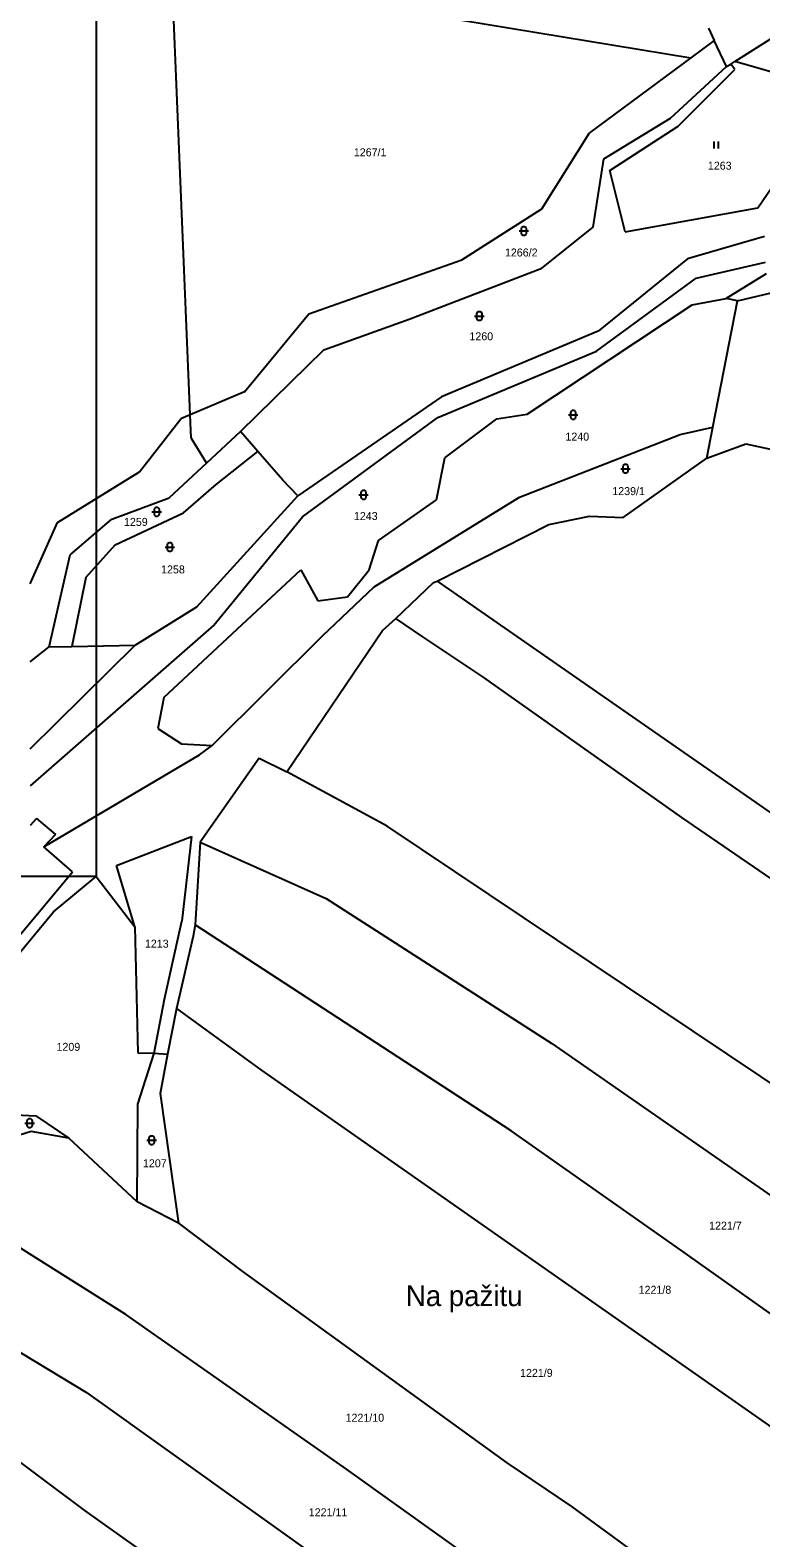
# Model space of a CAD drawing. Extents: x -799786 to -795190, y -1021716 to -1017834.
# Drawn here: x -798434.2 to -798278.5, y -1019350.1 to -1019029 of the extents above; entities that cross this region are included whole.
import ezdxf

# ---------------------------------------------------------------- set-up
doc = ezdxf.new("R2010")
doc.units = 0
for name, color, linetype in [('Default', 7, 'Continuous'), ('KN_HRANICE', 7, 'Continuous'), ('KN_KULTURY', 7, 'Continuous'), ('KN_PARCELY', 7, 'Continuous'), ('LEGENDA', 7, 'Continuous')]:
    doc.layers.add(name, color=color, linetype=linetype)

# ---------------------------------------------------------------- blocks, each defined once
blk = doc.blocks.new('306')
at = {"layer": 'Default'}
for p, q in [((-0.5, 1.5), (-0.5, 0)), ((0.5, 0), (0.5, 1.5))]:
    blk.add_line(p, q, dxfattribs=at)
blk = doc.blocks.new('316')
at = {"layer": 'Default'}
for points in [[(-1, 1), (0.27, 1), (1, 1)], [(-0.5, 1.5), (-0.4, 1.79), (-0.15, 1.97), (0.16, 1.97), (0.41, 1.79), (0.51, 1.5), (0.51, 0.5), (0.41, 0.21), (0.16, 0.03), (-0.15, 0.03), (-0.4, 0.21), (-0.5, 0.5), (-0.5, 1.5)]]:
    blk.add_lwpolyline(points, dxfattribs=at)

msp = doc.modelspace()

# ---------------------------------------------------------------- linework, layer by layer
at = {"layer": 'KN_HRANICE'}
for p, q in [((-798400.12, -1019110.95), (-798404.09, -1019014.54)), ((-798359.05, -1019024.1), (-798293.45, -1019034.91)), ((-798284.03, -1019035.68), (-798271.37, -1019027.66)), ((-798289.67, -1019028.59), (-798288.5, -1019031.25)), ((-798288.5, -1019031.25), (-798293.45, -1019034.91)), ((-798285.82, -1019036.77), (-798288.5, -1019031.25)), ((-798293.45, -1019034.91), (-798315.04, -1019050.85)), ((-798297.8, -1019047.77), (-798285.82, -1019036.77)), ((-798285.82, -1019036.77), (-798284.92, -1019036.23)), ((-798284.92, -1019036.23), (-798284.03, -1019035.68)), ((-798284.03, -1019037.42), (-798284.92, -1019036.23)), ((-798268.28, -1019040.2), (-798284.03, -1019035.68)), ((-798296.11, -1019049.46), (-798284.03, -1019037.42)), ((-798311.96, -1019056.41), (-798297.8, -1019047.77)), ((-798310.72, -1019058.9), (-798296.11, -1019049.46)), ((-798325.18, -1019067.07), (-798315.04, -1019050.85)), ((-798279.13, -1019066.87), (-798269.48, -1019052.64)), ((-798314.25, -1019070.99), (-798311.96, -1019056.41)), ((-798307.44, -1019071.99), (-798310.72, -1019058.9)), ((-798342.22, -1019077.92), (-798325.18, -1019067.07)), ((-798307.44, -1019071.99), (-798279.13, -1019066.87)), ((-798325.18, -1019079.73), (-798314.25, -1019070.99)), ((-798277.73, -1019072.94), (-798294.15, -1019077.72)), ((-798374.85, -1019089.46), (-798342.22, -1019077.92)), ((-798294.15, -1019077.72), (-798313.2, -1019093.11)), ((-798292.31, -1019081.83), (-798277.52, -1019078.42)), ((-798353.46, -1019090.56), (-798325.18, -1019079.73)), ((-798313.51, -1019097.35), (-798292.31, -1019081.83)), ((-798277.42, -1019080.9), (-798285.9, -1019086.17)), ((-798283.51, -1019086.63), (-798272.14, -1019083.99)), ((-798328.29, -1019110.8), (-798293.14, -1019087.52)), ((-798293.14, -1019087.52), (-798285.9, -1019086.17)), ((-798288.76, -1019113.55), (-798283.51, -1019086.63)), ((-798283.51, -1019086.63), (-798285.9, -1019086.17)), ((-798388.54, -1019106.05), (-798374.85, -1019089.46)), ((-798371.66, -1019097.13), (-798353.46, -1019090.56)), ((-798313.2, -1019093.11), (-798346.6, -1019107.08)), ((-798389.43, -1019114.51), (-798371.66, -1019097.13)), ((-798347.32, -1019111.52), (-798313.51, -1019097.35)), ((-798388.54, -1019106.05), (-798400.12, -1019110.95)), ((-798346.6, -1019107.08), (-798377.17, -1019128.23)), ((-798400.12, -1019110.95), (-798402.14, -1019111.8)), ((-798399.92, -1019115.9), (-798400.12, -1019110.95)), ((-798334.81, -1019111.83), (-798328.29, -1019110.8)), ((-798410.89, -1019123.09), (-798402.14, -1019111.8)), ((-798376.17, -1019132.7), (-798347.32, -1019111.52)), ((-798345.85, -1019120.08), (-798334.81, -1019111.83)), ((-798295.7, -1019115.11), (-798288.76, -1019113.55)), ((-798290.05, -1019120.17), (-798288.76, -1019113.55)), ((-798399.92, -1019115.9), (-798396.65, -1019121.23)), ((-798389.43, -1019114.51), (-798396.65, -1019121.23)), ((-798385.72, -1019118.74), (-798389.43, -1019114.51)), ((-798329.93, -1019128.46), (-798295.7, -1019115.11)), ((-798290.05, -1019120.17), (-798281.71, -1019117.15)), ((-798281.71, -1019117.15), (-798270.95, -1019119.48)), ((-798394.6, -1019125.76), (-798385.72, -1019118.74)), ((-798380.38, -1019124.89), (-798385.72, -1019118.74)), ((-798347.61, -1019129.08), (-798345.85, -1019120.08)), ((-798307.85, -1019132.82), (-798290.05, -1019120.17)), ((-798428.38, -1019133.84), (-798410.89, -1019123.09)), ((-798396.65, -1019121.23), (-798404.61, -1019128.63)), ((-798401.54, -1019131.84), (-798394.6, -1019125.76)), ((-798377.17, -1019128.23), (-798380.38, -1019124.89)), ((-798416.83, -1019133.17), (-798404.61, -1019128.63)), ((-798398.71, -1019151.85), (-798377.17, -1019128.23)), ((-798360.92, -1019147.57), (-798329.93, -1019128.46)), ((-798359.99, -1019137.74), (-798347.61, -1019129.08)), ((-798425.69, -1019140.76), (-798416.83, -1019133.17)), ((-798416.1, -1019138.65), (-798401.54, -1019131.84)), ((-798395.06, -1019155.75), (-798376.17, -1019132.7)), ((-798323.68, -1019134.33), (-798315, -1019132.53)), ((-798315, -1019132.53), (-798307.85, -1019132.82)), ((-798434.21, -1019146.97), (-798428.38, -1019133.84)), ((-798347.52, -1019146.35), (-798323.68, -1019134.33)), ((-798422.35, -1019145.57), (-798416.1, -1019138.65)), ((-798361.95, -1019143.95), (-798359.99, -1019137.74)), ((-798430.16, -1019160.33), (-798425.69, -1019140.76)), ((-798422.35, -1019145.57), (-798425.35, -1019160.26)), ((-798405.77, -1019171.12), (-798376.53, -1019143.95)), ((-798376.53, -1019143.95), (-798372.91, -1019150.57)), ((-798366.6, -1019149.74), (-798361.95, -1019143.95)), ((-798348.29, -1019146.68), (-798347.52, -1019146.35)), ((-798347.52, -1019146.35), (-798176.91, -1019264.88)), ((-798371.95, -1019157.98), (-798360.92, -1019147.57)), ((-798356.31, -1019154.31), (-798348.29, -1019146.68)), ((-798411.87, -1019160), (-798398.71, -1019151.85)), ((-798372.91, -1019150.57), (-798366.6, -1019149.74)), ((-798395.06, -1019155.75), (-798434.21, -1019189.94)), ((-798359.11, -1019156.9), (-798356.31, -1019154.31)), ((-798350.55, -1019158.22), (-798356.31, -1019154.31)), ((-798395.43, -1019181.36), (-798371.95, -1019157.98)), ((-798379.56, -1019186.95), (-798359.11, -1019156.9)), ((-798337.52, -1019166.91), (-798350.55, -1019158.22)), ((-798434.21, -1019182.07), (-798411.87, -1019160)), ((-798434.21, -1019163.57), (-798430.16, -1019160.33)), ((-798430.16, -1019160.33), (-798425.35, -1019160.26)), ((-798425.35, -1019160.26), (-798411.87, -1019160)), ((-798295.35, -1019196.67), (-798337.52, -1019166.91)), ((-798405.77, -1019171.12), (-798407.01, -1019177.74)), ((-798407.01, -1019177.74), (-798401.94, -1019181.05)), ((-798401.94, -1019181.05), (-798395.43, -1019181.36)), ((-798398.13, -1019183.37), (-798395.43, -1019181.36)), ((-798431.28, -1019202.97), (-798398.13, -1019183.37)), ((-798385.45, -1019184.05), (-798397.97, -1019201.95)), ((-798385.45, -1019184.05), (-798379.56, -1019186.95)), ((-798358.17, -1019198.54), (-798379.56, -1019186.95)), ((-798432.88, -1019196.92), (-798434.21, -1019198.43)), ((-798432.88, -1019196.92), (-798428.85, -1019200.33)), ((-798236.26, -1019237.37), (-798295.35, -1019196.67)), ((-798428.85, -1019200.33), (-798431.28, -1019202.97)), ((-798415.85, -1019206.94), (-798399.81, -1019200.77)), ((-798399.81, -1019200.77), (-798401.87, -1019218.77)), ((-798269.58, -1019257.87), (-798358.17, -1019198.54)), ((-798425.19, -1019208.25), (-798431.28, -1019202.97)), ((-798397.97, -1019201.95), (-798399.08, -1019219.6)), ((-798397.97, -1019201.95), (-798371.17, -1019213.94)), ((-798411.9, -1019220.01), (-798415.85, -1019206.94)), ((-798458.53, -1019248.28), (-798425.19, -1019208.25)), ((-798429.28, -1019216.81), (-798420.18, -1019209.26)), ((-798420.18, -1019209.26), (-798411.9, -1019220.01)), ((-798371.17, -1019213.94), (-798323.08, -1019244.85)), ((-798456.62, -1019249.78), (-798429.28, -1019216.81)), ((-798411.9, -1019220.01), (-798411.26, -1019246.84)), ((-798405.6, -1019235.43), (-798401.87, -1019218.77)), ((-798399.08, -1019219.6), (-798399.5, -1019221.98)), ((-798331.7, -1019263.44), (-798399.08, -1019219.6)), ((-798399.5, -1019221.98), (-798403.01, -1019237.4)), ((-798407.77, -1019246.91), (-798405.6, -1019235.43)), ((-798403.01, -1019237.4), (-798404.98, -1019247.1)), ((-798403.01, -1019237.4), (-798385.05, -1019250.48)), ((-798323.08, -1019244.85), (-798216.61, -1019318.7)), ((-798411.28, -1019257.77), (-798407.77, -1019246.91)), ((-798411.26, -1019246.84), (-798407.77, -1019246.91)), ((-798407.77, -1019246.91), (-798404.98, -1019247.1)), ((-798404.98, -1019247.1), (-798406.53, -1019255.48)), ((-798385.05, -1019250.48), (-798240.9, -1019351.36)), ((-798406.53, -1019255.48), (-798402.6, -1019283.09)), ((-798411.39, -1019278.54), (-798411.28, -1019257.77)), ((-798441.91, -1019259.81), (-798433.02, -1019260.22)), ((-798433.02, -1019260.22), (-798425.97, -1019264.99)), ((-798434, -1019263.58), (-798451.99, -1019269.12)), ((-798425.97, -1019264.99), (-798434, -1019263.58)), ((-798411.39, -1019278.54), (-798425.97, -1019264.99)), ((-798295.38, -1019289), (-798331.7, -1019263.44)), ((-798413.87, -1019302.58), (-798455.66, -1019276.2)), ((-798402.6, -1019283.09), (-798411.39, -1019278.54)), ((-798402.6, -1019283.09), (-798388.96, -1019293.42)), ((-798172.28, -1019376.09), (-798295.38, -1019289)), ((-798388.96, -1019293.42), (-798332.63, -1019334.12)), ((-798458.48, -1019297.36), (-798422.2, -1019319.14)), ((-798366.78, -1019335.52), (-798413.87, -1019302.58)), ((-798422.56, -1019344.32), (-798456.65, -1019318.8)), ((-798422.2, -1019319.14), (-798299.96, -1019406.46)), ((-798267.29, -1019406.58), (-798366.78, -1019335.52)), ((-798332.63, -1019334.12), (-798318.88, -1019343.43)), ((-798336.15, -1019405.61), (-798422.56, -1019344.32)), ((-798318.88, -1019343.43), (-798278.8, -1019372.75))]:
    msp.add_line(p, q, dxfattribs=at)
at = {"layer": 'LEGENDA'}
msp.add_lwpolyline([(-799014.18, -1018789.26), (-798420.18, -1018789.26), (-798420.18, -1019209.26), (-799014.18, -1019209.26)], close=True, dxfattribs=at)

# ---------------------------------------------------------------- block references
at = {"layer": 'KN_KULTURY'}
for name, p in [('306', (-798288.02, -1019054.24)), ('316', (-798329.03, -1019072.79)), ('316', (-798338.51, -1019090.9)), ('316', (-798318.49, -1019111.95)), ('316', (-798307.36, -1019123.42)), ('316', (-798363.18, -1019128.99)), ('316', (-798407.26, -1019132.6)), ('316', (-798404.46, -1019140.1)), ('316', (-798434.33, -1019262.8)), ('316', (-798408.33, -1019266.45))]:
    msp.add_blockref(name, p, dxfattribs=at)

# ---------------------------------------------------------------- texts
at = {"layer": 'KN_PARCELY'}
for s, height, p in [('1267/1', 1.7, (-798365.25, -1019055.88)), ('1263', 1.7, (-798289.81, -1019058.73)), ('1266/2', 1.7, (-798333.05, -1019077.22)), ('1260', 1.7, (-798340.62, -1019095.07)), ('1240', 1.7, (-798320.16, -1019116.44)), ('1239/1', 1.7, (-798310.17, -1019128.04)), ('1259', 1.7, (-798414.23, -1019134.59)), ('1243', 1.7, (-798365.23, -1019133.35)), ('1258', 1.7, (-798406.32, -1019144.72)), ('1213', 1.7, (-798409.77, -1019224.43)), ('1209', 1.7, (-798428.61, -1019246.4)), ('1207', 1.7, (-798410.19, -1019271.2)), ('1221/7', 1.7, (-798289.54, -1019284.48)), ('Na pažitu', 4.4, (-798354.16, -1019300.77)), ('1221/8', 1.7, (-798304.56, -1019298.14)), ('1221/9', 1.7, (-798329.83, -1019315.84)), ('1221/10', 1.7, (-798367.01, -1019325.39)), ('1221/11', 1.7, (-798374.86, -1019345.53))]:
    msp.add_text(s, height=height, dxfattribs=at).set_placement(p)

doc.saveas('drawing.dxf')
